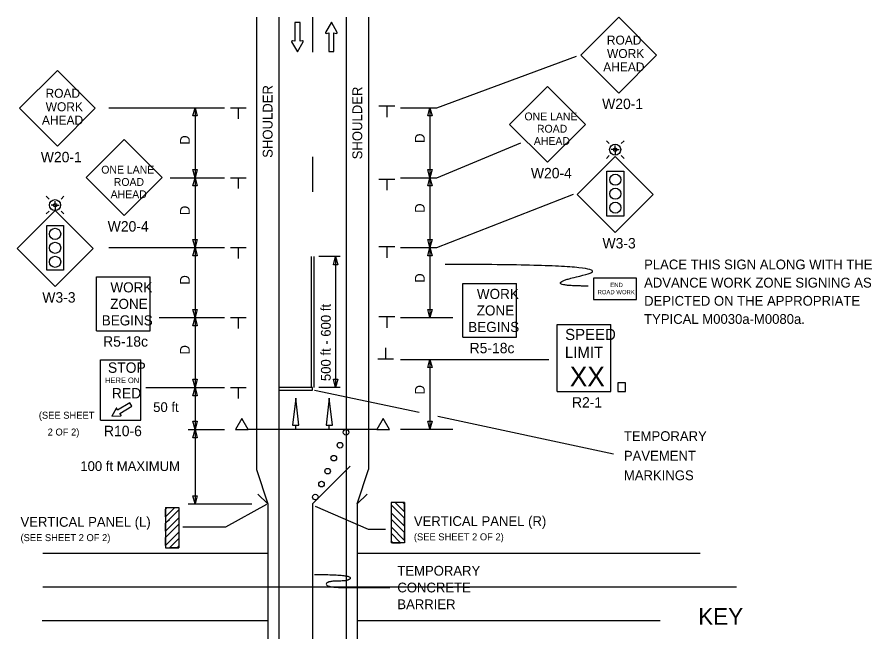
# Model space of a CAD drawing. Extents: x 16520 to 18479, y 5662 to 6927.
# Drawn here: x 16743 to 17354, y 6460 to 6899 of the extents above; entities that cross this region are included whole.
import ezdxf

# ---------------------------------------------------------------- set-up
doc = ezdxf.new("R2010")
doc.units = 0
for name, color, linetype in [('ALI_LEGAL_EX', 7, 'Continuous'), ('MT_SCRATCH_LEVEL_E', 7, 'Continuous'), ('PAVT_EDGE_EX', 7, 'Continuous'), ('TRAFFIC_SIGNS_PR', 7, 'Continuous'), ('TYPICAL_TEXT_DIMEN_EX', 7, 'Continuous'), ('TYPICAL_TEXT_DIMEN_PR', 7, 'Continuous')]:
    doc.layers.add(name, color=color, linetype=linetype)

msp = doc.modelspace()

# ---------------------------------------------------------------- linework, layer by layer
at = {"layer": 'ALI_LEGAL_EX'}
for points in [[(16953.78, 6899.43), (16953.78, 6874.43)], [(16953.78, 6799.43), (16953.78, 6774.43)], [(16952.78, 6728.2), (16952.78, 6634.57)], [(16954.78, 6728.2), (16954.78, 6634.57)]]:
    msp.add_lwpolyline(points, dxfattribs=at)
at = {"layer": 'MT_SCRATCH_LEVEL_E'}
for p, q in [((16944.86, 6895.47), (16941.11, 6895.47)), ((16941.11, 6895.47), (16941.11, 6882.21)), ((16944.86, 6895.47), (16941.11, 6895.47)), ((16941.11, 6895.47), (16941.11, 6882.21)), ((16944.86, 6882.21), (16944.86, 6895.47)), ((16944.86, 6882.21), (16944.86, 6895.47)), ((16967.25, 6895.73), (16963.14, 6888.49)), ((16967.25, 6895.73), (16963.14, 6888.49)), ((16971.4, 6888.49), (16967.25, 6895.73)), ((16971.4, 6888.49), (16967.25, 6895.73)), ((16963.62, 6887.8), (16965.4, 6888.12)), ((16963.62, 6887.8), (16965.4, 6888.12)), ((16965.4, 6888.12), (16965.4, 6874.86)), ((16965.4, 6888.12), (16965.4, 6874.86)), ((16969.14, 6874.86), (16969.14, 6888.12)), ((16969.14, 6888.12), (16970.92, 6887.8)), ((16969.14, 6874.86), (16969.14, 6888.12)), ((16969.14, 6888.12), (16970.92, 6887.8)), ((16938.86, 6881.84), (16943, 6874.6)), ((16938.86, 6881.84), (16943, 6874.6)), ((16941.11, 6882.21), (16939.34, 6882.53)), ((16941.11, 6882.21), (16939.34, 6882.53)), ((16943, 6874.6), (16947.12, 6881.84)), ((16943, 6874.6), (16947.12, 6881.84)), ((16946.63, 6882.53), (16944.86, 6882.21)), ((16946.63, 6882.53), (16944.86, 6882.21)), ((16965.4, 6874.86), (16969.14, 6874.86)), ((16965.4, 6874.86), (16969.14, 6874.86))]:
    msp.add_line(p, q, dxfattribs=at)
for centre, start, end in [((16963.54, 6888.26), 150.42484, 279.96381), ((16963.54, 6888.26), 150.42484, 279.96381), ((16970.99, 6888.26), 260.03619, 29.77312), ((16970.99, 6888.26), 260.03619, 29.77312), ((16939.27, 6882.06), 80.03619, 209.77312), ((16939.27, 6882.06), 80.03619, 209.77312), ((16946.71, 6882.07), 330.42484, 99.96381), ((16946.71, 6882.07), 330.42484, 99.96381)]:
    msp.add_arc(centre, 0.463, start, end, dxfattribs=at)
at = {"layer": 'PAVT_EDGE_EX'}
for p, q in [((16913.78, 6899.43), (16913.78, 6576.06)), ((16929.78, 6899.43), (16929.78, 6077.5)), ((16977.78, 6899.43), (16977.78, 6077.5)), ((16993.78, 6899.43), (16993.78, 6576.06)), ((16953.78, 6551.35), (16980.8, 6578.37)), ((16913.78, 6576.06), (16921.78, 6551.35)), ((16985.78, 6551.35), (16993.78, 6576.06)), ((16921.78, 6551.35), (16914.71, 6558.43)), ((16985.78, 6551.35), (16992.85, 6558.43)), ((16921.78, 6551.35), (16921.78, 6419.96)), ((16953.78, 6551.35), (16953.78, 6419.96)), ((16985.78, 6551.35), (16985.78, 6419.96)), ((16760.93, 6516.09), (16921.78, 6516.09)), ((16985.78, 6516.09), (17230.97, 6516.09)), ((16760.93, 6492.09), (17256.97, 6492.09)), ((16760.41, 6468.09), (16921.78, 6468.09)), ((16985.78, 6468.09), (17202.32, 6468.09))]:
    msp.add_line(p, q, dxfattribs=at)
for points in [[(16760.93, 6492.09), (16785.93, 6492.09)], [(16860.93, 6492.09), (16885.93, 6492.09)], [(17060.93, 6492.09), (17085.93, 6492.09)], [(17160.93, 6492.09), (17185.93, 6492.09)]]:
    msp.add_lwpolyline(points, dxfattribs=at)
at = {"layer": 'TRAFFIC_SIGNS_PR'}
for p, q in [((17172.72, 6899.41), (17145.57, 6872.26)), ((17199.87, 6872.26), (17172.72, 6899.41)), ((17145.57, 6872.26), (17172.72, 6845.1)), ((17172.72, 6845.1), (17199.87, 6872.26)), ((16771.3, 6861.36), (16744.15, 6834.21)), ((16798.46, 6834.21), (16771.3, 6861.36)), ((17121.76, 6849.9), (17094.61, 6822.74)), ((17148.92, 6822.74), (17121.76, 6849.9)), ((16744.15, 6834.21), (16771.3, 6807.06)), ((16771.3, 6807.06), (16798.46, 6834.21)), ((17094.61, 6822.74), (17121.76, 6795.59)), ((17121.76, 6795.59), (17148.92, 6822.74)), ((16819.13, 6811.82), (16791.98, 6784.67)), ((16846.28, 6784.67), (16819.13, 6811.82)), ((17165.93, 6808.95), (17163.9, 6810.98)), ((17174.5, 6808.95), (17176.53, 6810.98)), ((17170.21, 6804.67), (17167.34, 6804.67)), ((17170.21, 6804.67), (17170.21, 6807.55)), ((17170.21, 6804.67), (17170.21, 6800.73)), ((17170.21, 6804.67), (17173.09, 6804.67)), ((17170.28, 6799.75), (17143.13, 6772.6)), ((17165.93, 6800.39), (17163.9, 6798.36)), ((17197.44, 6772.6), (17170.28, 6799.75)), ((17176.53, 6798.36), (17174.5, 6800.39)), ((16791.98, 6784.67), (16819.13, 6757.52)), ((16819.13, 6757.52), (16846.28, 6784.67)), ((16765.39, 6769.27), (16763.35, 6771.3)), ((16769.67, 6764.98), (16769.67, 6767.86)), ((16773.95, 6769.27), (16775.98, 6771.3)), ((17143.13, 6772.6), (17170.28, 6745.45)), ((17170.28, 6745.45), (17197.44, 6772.6)), ((16769.67, 6761.05), (16742.52, 6733.89)), ((16769.67, 6764.98), (16766.79, 6764.98)), ((16769.67, 6764.98), (16769.67, 6761.05)), ((16769.67, 6764.98), (16772.55, 6764.98)), ((16796.82, 6733.89), (16769.67, 6761.05)), ((16765.39, 6760.7), (16763.35, 6758.67)), ((16775.98, 6758.67), (16773.95, 6760.7)), ((16742.52, 6733.89), (16769.67, 6706.74)), ((16769.67, 6706.74), (16796.82, 6733.89)), ((16799.24, 6675.21), (16799.24, 6713.61)), ((16799.24, 6713.61), (16837.64, 6713.61)), ((16837.64, 6675.21), (16837.64, 6713.61)), ((17061.31, 6670.51), (17061.31, 6708.91)), ((17061.31, 6708.91), (17099.71, 6708.91)), ((17099.71, 6670.51), (17099.71, 6708.91)), ((17128.67, 6679.66), (17167.07, 6679.66)), ((17128.67, 6631.66), (17128.67, 6679.66)), ((17167.07, 6631.66), (17167.07, 6679.66)), ((16799.24, 6675.21), (16837.64, 6675.21)), ((17061.31, 6670.51), (17099.71, 6670.51)), ((16802.25, 6654.42), (16831.05, 6654.42)), ((16802.25, 6611.22), (16802.25, 6654.42)), ((16816.65, 6654.42), (16816.65, 6654.42)), ((16831.05, 6611.22), (16831.05, 6654.42)), ((17128.67, 6631.66), (17167.07, 6631.66)), ((16802.25, 6611.22), (16831.05, 6611.22)), ((16999.78, 6604.57), (16907.78, 6604.57)), ((16941.78, 6604.57), (16941.78, 6607.59)), ((16965.78, 6604.57), (16965.78, 6607.59)), ((16848.65, 6548.76), (16858.25, 6548.76)), ((16848.65, 6548.76), (16848.65, 6519.96)), ((16848.65, 6547.67), (16849.74, 6548.76)), ((16848.65, 6542.01), (16855.4, 6548.76)), ((16848.65, 6548.76), (16858.25, 6548.76)), ((16848.65, 6548.76), (16848.65, 6519.96)), ((16848.65, 6547.67), (16849.74, 6548.76)), ((16848.65, 6542.01), (16855.4, 6548.76)), ((16848.65, 6537.49), (16858.25, 6547.09)), ((16848.65, 6537.49), (16858.25, 6547.09)), ((16858.25, 6548.76), (16858.25, 6519.96)), ((16858.25, 6548.76), (16858.25, 6519.96)), ((17019.53, 6552.35), (17009.93, 6552.35)), ((17009.93, 6552.35), (17009.93, 6523.55)), ((17019.53, 6552.35), (17009.93, 6552.35)), ((17009.93, 6552.35), (17009.93, 6523.55)), ((17019.53, 6541.08), (17009.93, 6550.68)), ((17019.53, 6541.08), (17009.93, 6550.68)), ((17019.53, 6545.6), (17012.78, 6552.35)), ((17019.53, 6545.6), (17012.78, 6552.35)), ((17019.53, 6551.26), (17018.44, 6552.35)), ((17019.53, 6551.26), (17018.44, 6552.35)), ((17019.53, 6552.35), (17019.53, 6523.55)), ((17019.53, 6552.35), (17019.53, 6523.55)), ((16848.65, 6531.83), (16858.25, 6541.43)), ((16848.65, 6531.83), (16858.25, 6541.43)), ((17019.53, 6535.42), (17009.93, 6545.02)), ((17019.53, 6535.42), (17009.93, 6545.02)), ((16848.65, 6527.3), (16858.25, 6536.9)), ((16848.65, 6527.3), (16858.25, 6536.9)), ((16850.07, 6538.9), (16851.48, 6540.31)), ((16850.07, 6538.9), (16851.48, 6540.31)), ((17019.53, 6530.9), (17009.93, 6540.5)), ((17019.53, 6530.9), (17009.93, 6540.5)), ((17019.53, 6525.24), (17009.93, 6534.84)), ((17019.53, 6525.24), (17009.93, 6534.84)), ((16848.65, 6521.65), (16858.25, 6531.25)), ((16848.65, 6521.65), (16858.25, 6531.25)), ((17016.7, 6523.55), (17009.93, 6530.31)), ((17016.7, 6523.55), (17009.93, 6530.31)), ((16851.49, 6519.96), (16858.25, 6526.72)), ((16851.49, 6519.96), (16858.25, 6526.72)), ((17011.04, 6523.55), (17009.93, 6524.66)), ((17011.04, 6523.55), (17009.93, 6524.66)), ((17019.53, 6523.55), (17009.93, 6523.55)), ((17019.53, 6523.55), (17009.93, 6523.55)), ((16848.65, 6519.96), (16858.25, 6519.96)), ((16848.65, 6519.96), (16858.25, 6519.96)), ((16857.15, 6519.96), (16858.25, 6521.06)), ((16857.15, 6519.96), (16858.25, 6521.06))]:
    msp.add_line(p, q, dxfattribs=at)
for points in [[(17176.35, 6757.15), (17164.35, 6757.15), (17164.35, 6789.15), (17176.35, 6789.15)], [(16775.73, 6718.44), (16763.73, 6718.44), (16763.73, 6750.44), (16775.73, 6750.44)], [(17154.75, 6697.48), (17185.47, 6697.48), (17185.47, 6712.84), (17154.75, 6712.84)], [(16929.78, 6634.57), (16929.78, 6632.57), (16953.78, 6632.57), (16953.78, 6634.57)], [(17172.09, 6631.66), (17177.68, 6631.66), (17177.68, 6637.83), (17172.09, 6637.83)], [(16944.03, 6607.59), (16941.78, 6627.01), (16939.53, 6607.59)], [(16968.03, 6607.59), (16965.78, 6627.01), (16963.53, 6607.59)], [(16907.78, 6604.57), (16903.28, 6612.37), (16898.78, 6604.57)], [(17008.78, 6604.57), (17004.28, 6612.37), (16999.78, 6604.57)], [(16849.74, 6548.76), (16855.4, 6548.76), (16848.65, 6542.01), (16848.65, 6547.67)], [(16849.74, 6548.76), (16855.4, 6548.76), (16848.65, 6542.01), (16848.65, 6547.67)], [(16848.65, 6537.49), (16858.25, 6547.09), (16858.25, 6541.43), (16848.65, 6531.83)], [(16848.65, 6537.49), (16858.25, 6547.09), (16858.25, 6541.43), (16848.65, 6531.83)], [(17019.53, 6541.08), (17009.93, 6550.68), (17009.93, 6545.02), (17019.53, 6535.42)], [(17019.53, 6541.08), (17009.93, 6550.68), (17009.93, 6545.02), (17019.53, 6535.42)], [(17018.44, 6552.35), (17012.78, 6552.35), (17019.53, 6545.6), (17019.53, 6551.26)], [(17018.44, 6552.35), (17012.78, 6552.35), (17019.53, 6545.6), (17019.53, 6551.26)], [(16848.65, 6527.3), (16858.25, 6536.9), (16858.25, 6531.25), (16848.65, 6521.65)], [(16848.65, 6527.3), (16858.25, 6536.9), (16858.25, 6531.25), (16848.65, 6521.65)], [(17019.53, 6530.9), (17009.93, 6540.5), (17009.93, 6534.84), (17019.53, 6525.24)], [(17019.53, 6530.9), (17009.93, 6540.5), (17009.93, 6534.84), (17019.53, 6525.24)], [(17009.93, 6530.31), (17009.93, 6524.66), (17011.04, 6523.55), (17016.7, 6523.55)], [(17009.93, 6530.31), (17009.93, 6524.66), (17011.04, 6523.55), (17016.7, 6523.55)], [(16858.25, 6526.72), (16858.25, 6521.06), (16857.15, 6519.96), (16851.49, 6519.96)], [(16858.25, 6526.72), (16858.25, 6521.06), (16857.15, 6519.96), (16851.49, 6519.96)]]:
    msp.add_lwpolyline(points, close=True, dxfattribs=at)
for points in [[(16816.85, 6614.87), (16815.93, 6615.9), (16824.59, 6621.26), (16823.08, 6623.7), (16814.42, 6618.34), (16813.91, 6619.63)], [(16813.26, 6619.67), (16810.22, 6614.03), (16816.61, 6614.28)]]:
    msp.add_lwpolyline(points, dxfattribs=at)
for centre, radius in [((17170.21, 6804.67), 3.94), ((17170.21, 6804.67), 1.28), ((17170.35, 6783.14), 4), ((17170.35, 6773.14), 4), ((16769.67, 6764.98), 3.94), ((17170.35, 6763.14), 4), ((16769.67, 6764.98), 1.28), ((16769.73, 6744.44), 4), ((16769.73, 6734.44), 4), ((16769.73, 6724.44), 4), ((16977.78, 6602.57), 2), ((16973.38, 6593.3), 2), ((16968.98, 6584.04), 2), ((16964.58, 6574.78), 2), ((16960.18, 6565.51), 2), ((16955.78, 6556.25), 2)]:
    msp.add_circle(centre, radius, dxfattribs=at)
for centre, radius, start, end in [((16813.58, 6619.5), 0.355, 21.71521, 151.42661), ((16816.59, 6614.63), 0.354, 272.17868, 41.91782)]:
    msp.add_arc(centre, radius, start, end, dxfattribs=at)
msp.add_open_spline([(17150.89, 6707.11), (17113.1, 6707.11), (17181.12, 6722.59), (17048.59, 6722.59)], degree=2, dxfattribs=at)
at = {"layer": 'TYPICAL_TEXT_DIMEN_PR'}
for p, q in [((17042.78, 6834.57), (17142.57, 6871.45)), ((16808.08, 6834.57), (16890.78, 6834.57)), ((16868.21, 6828.71), (16869.78, 6834.57)), ((16869.78, 6834.57), (16869.78, 6784.57)), ((16869.78, 6834.57), (16871.35, 6828.71)), ((16895.03, 6834.57), (16906.28, 6834.57)), ((16900.66, 6834.57), (16900.66, 6826.79)), ((17012.53, 6835.68), (17001.28, 6835.68)), ((17006.91, 6835.68), (17006.91, 6827.89)), ((17016.78, 6834.57), (17042.78, 6834.57)), ((17036.21, 6828.71), (17037.78, 6834.57)), ((17037.78, 6834.57), (17037.78, 6784.57)), ((17037.78, 6834.57), (17039.35, 6828.71)), ((16869.78, 6828.71), (16868.21, 6828.71)), ((16871.35, 6828.71), (16869.78, 6828.71)), ((17037.78, 6828.71), (17036.21, 6828.71)), ((17039.35, 6828.71), (17037.78, 6828.71)), ((17042.78, 6784.57), (17102.74, 6809.53)), ((16869.78, 6784.57), (16868.21, 6790.43)), ((16868.21, 6790.43), (16869.78, 6790.43)), ((16869.78, 6784.57), (16868.21, 6790.43)), ((16868.21, 6790.43), (16869.78, 6790.43)), ((16869.78, 6790.43), (16871.35, 6790.43)), ((16871.35, 6790.43), (16869.78, 6784.57)), ((16869.78, 6790.43), (16871.35, 6790.43)), ((16871.35, 6790.43), (16869.78, 6784.57)), ((17037.78, 6784.57), (17036.21, 6790.43)), ((17036.21, 6790.43), (17037.78, 6790.43)), ((17037.78, 6790.43), (17039.35, 6790.43)), ((17039.35, 6790.43), (17037.78, 6784.57)), ((16852, 6784.57), (16890.78, 6784.57)), ((16868.21, 6778.71), (16869.78, 6784.57)), ((16869.78, 6784.57), (16869.78, 6734.57)), ((16869.78, 6784.57), (16871.35, 6778.71)), ((16895.03, 6784.57), (16906.28, 6784.57)), ((16900.66, 6784.57), (16900.66, 6776.79)), ((17012.53, 6783.38), (17001.28, 6783.38)), ((17006.91, 6783.38), (17006.91, 6775.6)), ((17016.78, 6784.57), (17042.78, 6784.57)), ((17036.21, 6778.71), (17037.78, 6784.57)), ((17037.78, 6784.57), (17037.78, 6734.57)), ((17037.78, 6784.57), (17039.35, 6778.71)), ((16869.78, 6778.71), (16868.21, 6778.71)), ((16871.35, 6778.71), (16869.78, 6778.71)), ((17037.78, 6778.71), (17036.21, 6778.71)), ((17039.35, 6778.71), (17037.78, 6778.71)), ((17042.78, 6734.57), (17140.34, 6772.73)), ((16869.78, 6734.57), (16868.21, 6740.43)), ((16868.21, 6740.43), (16869.78, 6740.43)), ((16869.78, 6740.43), (16871.35, 6740.43)), ((16871.35, 6740.43), (16869.78, 6734.57)), ((17037.78, 6734.57), (17036.21, 6740.43)), ((17036.21, 6740.43), (17037.78, 6740.43)), ((17037.78, 6740.43), (17039.35, 6740.43)), ((17039.35, 6740.43), (17037.78, 6734.57)), ((16808.08, 6734.57), (16890.78, 6734.57)), ((16868.21, 6728.71), (16869.78, 6734.57)), ((16869.78, 6734.57), (16871.35, 6728.71)), ((16869.78, 6734.57), (16869.78, 6684.57)), ((16895.03, 6734.57), (16906.28, 6734.57)), ((16900.66, 6734.57), (16900.66, 6726.79)), ((17012.53, 6735.05), (17001.28, 6735.05)), ((17006.91, 6735.05), (17006.91, 6727.26)), ((17016.78, 6734.57), (17042.78, 6734.57)), ((17036.21, 6728.71), (17037.78, 6734.57)), ((17037.78, 6734.57), (17037.78, 6684.57)), ((17037.78, 6734.57), (17039.35, 6728.71)), ((16869.78, 6728.71), (16868.21, 6728.71)), ((16871.35, 6728.71), (16869.78, 6728.71)), ((16973.59, 6728.2), (16958.31, 6728.2)), ((16968.72, 6722.34), (16970.29, 6728.2)), ((16970.29, 6728.2), (16970.29, 6634.57)), ((16970.29, 6728.2), (16971.86, 6722.34)), ((17037.78, 6728.71), (17036.21, 6728.71)), ((17039.35, 6728.71), (17037.78, 6728.71)), ((16970.29, 6722.34), (16968.72, 6722.34)), ((16971.86, 6722.34), (16970.29, 6722.34)), ((16869.78, 6684.57), (16868.21, 6690.43)), ((16868.21, 6690.43), (16869.78, 6690.43)), ((16869.78, 6690.43), (16871.35, 6690.43)), ((16871.35, 6690.43), (16869.78, 6684.57)), ((17037.78, 6684.57), (17036.21, 6690.43)), ((17036.21, 6690.43), (17037.78, 6690.43)), ((17037.78, 6690.43), (17039.35, 6690.43)), ((17039.35, 6690.43), (17037.78, 6684.57)), ((16844.01, 6684.57), (16890.78, 6684.57)), ((16868.21, 6678.71), (16869.78, 6684.57)), ((16869.78, 6684.57), (16869.78, 6634.57)), ((16869.78, 6684.57), (16871.35, 6678.71)), ((16895.03, 6684.57), (16906.28, 6684.57)), ((16900.66, 6684.57), (16900.66, 6676.79)), ((17012.53, 6685.05), (17001.28, 6685.05)), ((17006.91, 6685.05), (17006.91, 6677.26)), ((17016.78, 6684.57), (17054.02, 6684.57)), ((16869.78, 6678.71), (16868.21, 6678.71)), ((16871.35, 6678.71), (16869.78, 6678.71)), ((17006.14, 6655.16), (17006.14, 6662.94)), ((17000.52, 6655.16), (17011.77, 6655.16)), ((17016.78, 6654.68), (17122.84, 6654.68)), ((17036.21, 6648.82), (17037.78, 6654.68)), ((17037.78, 6654.68), (17037.78, 6604.68)), ((17037.78, 6654.68), (17039.35, 6648.82)), ((17037.78, 6648.82), (17036.21, 6648.82)), ((17039.35, 6648.82), (17037.78, 6648.82)), ((16869.78, 6634.57), (16868.21, 6640.43)), ((16868.21, 6640.43), (16869.78, 6640.43)), ((16869.78, 6640.43), (16871.35, 6640.43)), ((16871.35, 6640.43), (16869.78, 6634.57)), ((16970.29, 6634.57), (16968.72, 6640.43)), ((16968.72, 6640.43), (16970.29, 6640.43)), ((16970.29, 6640.43), (16971.86, 6640.43)), ((16971.86, 6640.43), (16970.29, 6634.57)), ((16834.5, 6634.57), (16890.78, 6634.57)), ((16868.21, 6628.71), (16869.78, 6634.57)), ((16869.78, 6634.57), (16869.78, 6604.57)), ((16869.78, 6634.57), (16871.35, 6628.71)), ((16895.03, 6634.57), (16906.28, 6634.57)), ((16900.66, 6634.57), (16900.66, 6626.79)), ((16955.27, 6632.78), (17030.03, 6616.85)), ((16973.59, 6634.57), (16958.31, 6634.57)), ((16869.78, 6628.71), (16868.21, 6628.71)), ((16871.35, 6628.71), (16869.78, 6628.71)), ((16869.78, 6604.57), (16868.21, 6610.43)), ((16868.21, 6610.43), (16869.78, 6610.43)), ((16869.78, 6610.43), (16871.35, 6610.43)), ((16871.35, 6610.43), (16869.78, 6604.57)), ((17037.78, 6604.68), (17036.21, 6610.54)), ((17036.21, 6610.54), (17037.78, 6610.54)), ((17037.78, 6610.54), (17039.35, 6610.54)), ((17039.35, 6610.54), (17037.78, 6604.68)), ((17043.46, 6613.99), (17169.05, 6587.22)), ((16864.78, 6604.57), (16890.78, 6604.57)), ((16868.21, 6598.71), (16869.78, 6604.57)), ((16869.78, 6604.57), (16871.35, 6598.71)), ((16869.78, 6604.57), (16869.78, 6551.35)), ((17016.78, 6604.68), (17054.02, 6604.68)), ((16869.78, 6598.71), (16868.21, 6598.71)), ((16871.35, 6598.71), (16869.78, 6598.71)), ((16869.78, 6551.35), (16868.21, 6557.22)), ((16868.21, 6557.22), (16869.78, 6557.22)), ((16869.78, 6557.22), (16871.35, 6557.22)), ((16871.35, 6557.22), (16869.78, 6551.35)), ((16864.78, 6551.35), (16910.48, 6551.35)), ((16920.82, 6551.01), (16891.56, 6534.78)), ((16920.82, 6551.01), (16891.56, 6534.78)), ((16955.78, 6549.81), (16993.57, 6533.37)), ((16955.78, 6549.81), (16993.57, 6533.37)), ((16891.56, 6534.78), (16860.98, 6534.78)), ((16891.56, 6534.78), (16860.98, 6534.78)), ((16993.57, 6533.37), (17006.03, 6533.37)), ((16993.57, 6533.37), (17006.03, 6533.37))]:
    msp.add_line(p, q, dxfattribs=at)
msp.add_open_spline([(16955.22, 6500.88), (16980.8, 6500.88), (16980.8, 6496.18), (16963.59, 6496.18), (16963.59, 6491.47), (16996.58, 6491.47), (17009.05, 6491.47)], degree=2, dxfattribs=at)

# ---------------------------------------------------------------- texts
at = {"layer": 'TRAFFIC_SIGNS_PR'}
for s, height, p in [('ROAD', 6.4, (17164.26, 6879.79)), ('WORK', 6.4, (17164.37, 6870.19)), ('AHEAD', 6.4, (17161.68, 6860.59)), ('ROAD', 6.4, (16762.85, 6841.74)), ('W20-1', 7.44, (17160.89, 6833.67)), ('WORK', 6.4, (16762.96, 6832.14)), ('AHEAD', 6.4, (16760.27, 6822.54)), ('ONE LANE', 5.6, (17105.35, 6825.61)), ('ROAD', 5.6, (17114.3, 6816.82)), ('AHEAD', 5.6, (17112.06, 6808.02)), ('W20-1', 7.44, (16759.47, 6795.62)), ('ONE LANE', 5.6, (16802.71, 6787.54)), ('W20-4', 7.44, (17109.94, 6784.15)), ('ROAD', 5.6, (16811.66, 6778.74)), ('AHEAD', 5.6, (16809.42, 6769.94)), ('W20-4', 7.44, (16807.31, 6746.08)), ('W3-3', 7.44, (17161.15, 6734.01)), ('PLACE THIS SIGN ALONG WITH THE', 7, (17190.9, 6719.06)), ('ADVANCE WORK ZONE SIGNING AS', 7, (17190.9, 6706.06)), ('WORK', 7.217, (16809.24, 6702.58)), ('END', 3.065, (17166.75, 6706.38)), ('W3-3', 7.44, (16760.54, 6695.3)), ('WORK', 7.217, (17071.31, 6697.88)), ('ROAD WORK', 3.065, (17157.63, 6701.27)), ('DEPICTED ON THE APPROPRIATE', 7, (17190.9, 6693.06)), ('ZONE', 7.217, (16809.12, 6690.77)), ('ZONE', 7.217, (17071.19, 6686.07)), ('BEGINS', 7.217, (16803.05, 6678.96)), ('BEGINS', 7.217, (17065.12, 6674.26)), ('TYPICAL M0030a-M0080a.', 7, (17190.9, 6680.06)), ('SPEED', 8, (17134.44, 6668.52)), ('R5-18c', 7.44, (16804.05, 6663.77)), ('R5-18c', 7.44, (17066.12, 6659.07)), ('LIMIT', 8, (17134.28, 6655.72)), ('STOP', 7.44, (16807.46, 6645.08)), ('XX', 14.031, (17137.78, 6635.42)), ('HERE ON', 4, (16805.46, 6637.72)), ('RED', 7.44, (16810.26, 6626.77)), ('R2-1', 7.44, (17139.35, 6620.22)), ('R10-6', 7.44, (16804.64, 6599.78))]:
    msp.add_text(s, height=height, dxfattribs=at).set_placement(p)
at = {"layer": 'TYPICAL_TEXT_DIMEN_EX'}
msp.add_text('KEY', height=12, dxfattribs=at).set_placement((17229.62, 6464.89))
at = {"layer": 'TYPICAL_TEXT_DIMEN_PR'}
for s, p in [('SHOULDER', (16925.2, 6798.81)), ('SHOULDER', (16989.31, 6797.73)), ('D', (16866, 6808.14)), ('D', (17034, 6809.45)), ('D', (16866, 6757.8)), ('D', (17034, 6759.45)), ('D', (16866, 6708.14)), ('D', (17034, 6709.45)), ('500 ft - 600 ft', (16966.8, 6639.16)), ('D', (16866, 6658.14)), ('D', (17034, 6629.56))]:
    msp.add_text(s, height=7, rotation=90, dxfattribs=at).set_placement(p)
for s, height, p in [('50 ft', 7, (16839.83, 6617.04)), ('(SEE SHEET', 5, (16758.05, 6612.24)), ('2 OF 2)', 5, (16764.38, 6600.24)), ('TEMPORARY', 7, (17176.44, 6596.31)), ('PAVEMENT', 7, (17176.44, 6582.31)), ('100 ft MAXIMUM', 7, (16787.74, 6574.88)), ('MARKINGS', 7, (17176.44, 6568.31)), ('VERTICAL PANEL (L)', 7, (16744.95, 6534.99)), ('VERTICAL PANEL (L)', 7, (16744.95, 6534.99)), ('VERTICAL PANEL (R)', 7, (17026.27, 6535.55)), ('VERTICAL PANEL (R)', 7, (17026.27, 6535.55)), ('(SEE SHEET 2 OF 2)', 5, (16744.95, 6524.74)), ('(SEE SHEET 2 OF 2)', 5, (16744.95, 6524.74)), ('(SEE SHEET 2 OF 2)', 5, (17026.27, 6525.3)), ('(SEE SHEET 2 OF 2)', 5, (17026.27, 6525.3)), ('TEMPORARY', 7, (17014.45, 6500.07)), ('CONCRETE', 7, (17014.45, 6488.07)), ('BARRIER', 7, (17014.45, 6476.07))]:
    msp.add_text(s, height=height, dxfattribs=at).set_placement(p)

doc.saveas('drawing.dxf')
